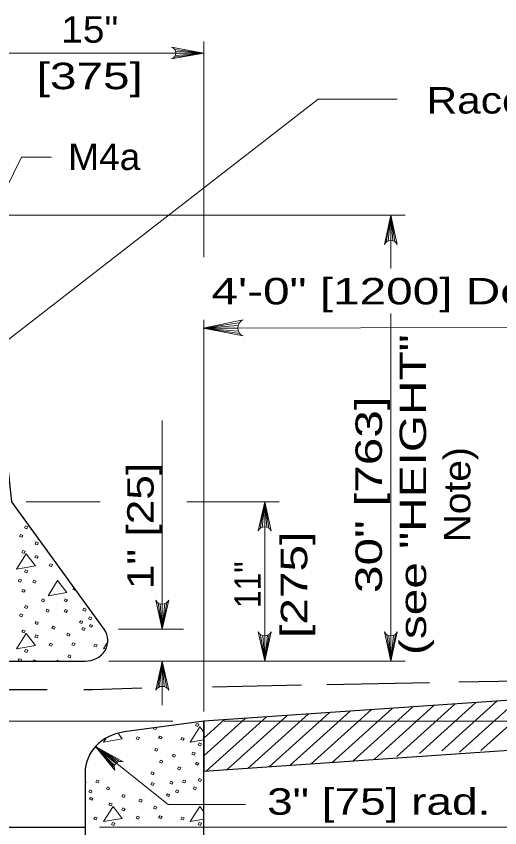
# Model space of a CAD drawing. Extents: x 1083.1 to 1123, y 697.4 to 741.4.
# Drawn here: x 1094.054 to 1096.906, y 703.761 to 708.543 of the extents above; entities that cross this region are included whole.
import ezdxf
from ezdxf.enums import TextEntityAlignment as Align

# ---------------------------------------------------------------- set-up
doc = ezdxf.new("R2010")
doc.units = 0
doc.header["$LTSCALE"] = 0.062
doc.layers.add('1', color=7, linetype='Continuous', lineweight=13)

msp = doc.modelspace()

# ---------------------------------------------------------------- linework, layer by layer
at = {"layer": '1'}
for p, q in [((1095.16083, 707.12275), (1095.16083, 708.39542)), ((1094.986, 708.30242), (1095.16083, 708.32642)), ((1094.98808, 708.34817), (1095.16083, 708.32642)), ((1094.99267, 708.3125), (1095.16083, 708.32642)), ((1094.99392, 708.33742), (1095.16083, 708.32642)), ((1094.99567, 708.32642), (1095.16083, 708.32642)), ((1093.45608, 706.21192), (1095.83508, 708.05542)), ((1095.83508, 708.05542), (1096.3005, 708.05542)), ((1093.92825, 707.3705), (1096.348, 707.3705)), ((1096.237, 707.21317), (1096.26375, 707.3705)), ((1096.24825, 707.21917), (1096.26375, 707.3705)), ((1096.26375, 707.22192), (1096.26375, 707.3705)), ((1096.27592, 707.22033), (1096.26375, 707.3705)), ((1096.28792, 707.215), (1096.26375, 707.3705)), ((1096.26375, 707.3705), (1096.26375, 707.05658)), ((1096.26375, 706.79183), (1096.26375, 704.74317)), ((1095.36967, 706.73608), (1095.15642, 706.70625)), ((1095.16083, 704.44592), (1095.16083, 706.75408)), ((1095.3625, 706.72133), (1095.15642, 706.70625)), ((1099.309, 706.71308), (1095.15642, 706.70625)), ((1095.36025, 706.70625), (1095.15642, 706.70625)), ((1095.364, 706.68708), (1095.15642, 706.70625)), ((1095.37217, 706.67333), (1095.15642, 706.70625)), ((1094.91525, 706.16133), (1094.91525, 704.93058)), ((1094.11258, 705.68267), (1094.54875, 705.68267)), ((1095.05925, 705.68267), (1095.604, 705.68267)), ((1095.493, 705.52533), (1095.51975, 705.68267)), ((1095.50425, 705.53133), (1095.51975, 705.68267)), ((1095.51975, 705.68267), (1095.51975, 704.74317)), ((1095.51975, 705.53408), (1095.51975, 705.68267)), ((1095.532, 705.5325), (1095.51975, 705.68267)), ((1095.54392, 705.52717), (1095.51975, 705.68267)), ((1094.89108, 705.08608), (1094.91525, 704.93058)), ((1094.903, 705.08075), (1094.91525, 704.93058)), ((1094.94192, 705.08792), (1094.91525, 704.93058)), ((1094.93075, 705.08192), (1094.91525, 704.93058)), ((1094.91525, 705.07917), (1094.91525, 704.93058)), ((1094.65667, 704.93058), (1095.03958, 704.93058)), ((1095.49558, 704.89867), (1095.51975, 704.74317)), ((1095.50758, 704.89342), (1095.51975, 704.74317)), ((1095.5465, 704.9005), (1095.51975, 704.74317)), ((1095.53525, 704.8945), (1095.51975, 704.74317)), ((1095.51975, 704.89175), (1095.51975, 704.74317)), ((1096.23958, 704.89867), (1096.26375, 704.74317)), ((1096.2515, 704.89342), (1096.26375, 704.74317)), ((1096.29042, 704.9005), (1096.26375, 704.74317)), ((1096.27925, 704.8945), (1096.26375, 704.74317)), ((1096.26375, 704.89175), (1096.26375, 704.74317)), ((1094.15425, 704.74317), (1094.15775, 704.75108)), ((1094.29692, 704.7495), (1094.293, 704.74317)), ((1094.30192, 704.74317), (1094.29692, 704.7495)), ((1094.4675, 704.74517), (1094.46758, 704.74542)), ((1094.46758, 704.74542), (1094.46792, 704.74525)), ((1094.59983, 704.74317), (1096.348, 704.74317)), ((1094.8885, 704.58583), (1094.91525, 704.74317)), ((1094.89967, 704.59183), (1094.91525, 704.74317)), ((1094.91525, 704.59458), (1094.91525, 704.74317)), ((1094.92742, 704.59292), (1094.91525, 704.74317)), ((1094.93942, 704.58767), (1094.91525, 704.74317)), ((1094.91525, 704.48392), (1094.91525, 704.74317)), ((1096.29883, 704.18142), (1096.64175, 704.49)), ((1096.43342, 704.19975), (1096.7655, 704.4985)), ((1096.56525, 704.2155), (1096.88925, 704.50692)), ((1096.66892, 704.20575), (1097.01292, 704.51542)), ((1096.79442, 704.21592), (1097.13667, 704.52392)), ((1095.54592, 704.121), (1095.89942, 704.43917)), ((1095.66967, 704.1295), (1096.02317, 704.44767)), ((1095.79333, 704.138), (1096.14683, 704.45608)), ((1095.917, 704.14642), (1096.27058, 704.46458)), ((1096.04075, 704.15492), (1096.39433, 704.47308)), ((1096.23058, 704.22283), (1096.51808, 704.4815)), ((1095.16083, 704.18592), (1095.40458, 704.40517)), ((1095.16083, 704.28875), (1095.28083, 704.39675)), ((1095.17475, 704.0955), (1095.52825, 704.41367)), ((1095.29842, 704.104), (1095.65192, 704.42217)), ((1095.42217, 704.1125), (1095.77567, 704.43067)), ((1092.79442, 704.3885), (1094.97683, 704.3885)), ((1095.16083, 704.32433), (1095.1365, 704.35558)), ((1095.28075, 704.3885), (1100.93725, 704.3885)), ((1100.14858, 704.3885), (1096.461, 704.3885)), ((1096.1645, 704.16342), (1096.27725, 704.26483)), ((1094.64208, 704.14075), (1094.52225, 704.241)), ((1094.63433, 704.129), (1094.52225, 704.241)), ((1094.632, 704.11792), (1094.52225, 704.241)), ((1094.65117, 704.14733), (1094.52225, 704.241)), ((1094.66308, 704.15133), (1094.52225, 704.241)), ((1095.16083, 703.85558), (1095.1365, 703.88692)), ((1094.54408, 703.76442), (1100.20558, 703.76442))]:
    msp.add_line(p, q, dxfattribs=at)
at = {"layer": '1', "lineweight": 25}
for p, q in [((1092.1595, 704.74317), (1094.45958, 704.74317)), ((1096.66467, 704.62075), (1097.23042, 704.63183)), ((1094.795, 704.5835), (1094.50333, 704.57417)), ((1095.21092, 704.59225), (1095.73708, 704.60258)), ((1095.88567, 704.6055), (1096.49117, 704.61733)), ((1094.23692, 704.57392), (1093.65075, 704.57333)), ((1094.50333, 704.57417), (1094.45267, 704.57408)), ((1095.16083, 704.3885), (1094.68975, 704.32567)), ((1095.16083, 699.49442), (1095.16083, 704.3885)), ((1096.78842, 704.20617), (1099.30092, 704.37842)), ((1095.16083, 704.09458), (1096.78842, 704.20617)), ((1094.45983, 704.08583), (1094.45983, 702.96883)), ((1093.78567, 703.76442), (1094.45983, 703.76442))]:
    msp.add_line(p, q, dxfattribs=at)
at = {"layer": '1'}
for points in [[(1094.97, 708.29208), (1095.16083, 708.32642), (1094.97, 708.36083)], [(1095.16083, 708.32642), (1093.50392, 708.32642), (1092.759, 708.32642)], [(1093.70142, 706.93558), (1094.084, 707.71383), (1094.26242, 707.71383)], [(1096.22558, 707.19875), (1096.26375, 707.3705), (1096.30192, 707.19875)], [(1095.392, 706.65917), (1095.15642, 706.70625), (1095.392, 706.75342)], [(1095.48158, 705.51092), (1095.51975, 705.68267), (1095.55792, 705.51092)], [(1094.4025, 705.16558), (1094.40025, 705.16158), (1094.38675, 705.16642), (1094.393, 705.17858)], [(1094.95342, 705.10233), (1094.91525, 704.93058), (1094.87708, 705.10233)], [(1095.55792, 704.91492), (1095.51975, 704.74317), (1095.48158, 704.91492)], [(1096.30192, 704.91492), (1096.26375, 704.74317), (1096.22558, 704.91492)], [(1094.58817, 704.84883), (1094.56817, 704.8165), (1094.58192, 704.819)], [(1094.07342, 704.74317), (1094.06617, 704.74625), (1094.0715, 704.75758)], [(1094.0715, 704.75758), (1094.085, 704.75267), (1094.08083, 704.74317)], [(1094.15775, 704.75108), (1094.17125, 704.74542), (1094.17017, 704.74317)], [(1094.87708, 704.57142), (1094.91525, 704.74317), (1094.95342, 704.57142)], [(1094.88325, 704.3515), (1094.87783, 704.34025), (1094.86442, 704.34508), (1094.86633, 704.34925)], [(1095.1365, 704.35558), (1095.08083, 704.26592), (1095.16083, 704.27992)], [(1094.5815, 704.28617), (1094.56892, 704.26592), (1094.67942, 704.28525), (1094.65633, 704.31492)], [(1094.63633, 704.10092), (1094.52225, 704.241), (1094.68508, 704.14925)], [(1094.52225, 704.241), (1094.95042, 703.89883), (1095.40592, 703.89883)], [(1094.45983, 704.03275), (1094.46658, 704.02992), (1094.46117, 704.01858), (1094.45983, 704.01908)], [(1094.45983, 703.9165), (1094.46117, 703.916), (1094.45983, 703.91317)], [(1095.1365, 703.88692), (1095.08083, 703.79717), (1095.16083, 703.81125)]]:
    msp.add_lwpolyline(points, dxfattribs=at)
at = {"layer": '1', "lineweight": 25}
for points in [[(1094.57242, 704.93058), (1094.02833, 705.68267), (1093.86025, 707.22475)], [(1099.30092, 704.67233), (1095.16083, 704.3885), (1095.16083, 704.09458)]]:
    msp.add_lwpolyline(points, dxfattribs=at)
at = {"layer": '1'}
for points in [[(1094.10833, 705.53983), (1094.12183, 705.53417), (1094.11558, 705.52283), (1094.10208, 705.5285)], [(1094.07875, 705.48967), (1094.09217, 705.48408), (1094.08683, 705.47275), (1094.07333, 705.47842)], [(1094.17033, 705.44525), (1094.18375, 705.43958), (1094.17842, 705.42833), (1094.16492, 705.43317)], [(1094.09308, 705.39517), (1094.10658, 705.39033), (1094.10117, 705.37817), (1094.08767, 705.38383)], [(1094.11192, 705.37492), (1094.05625, 705.28525), (1094.16675, 705.30467)], [(1094.16942, 705.36608), (1094.18292, 705.36042), (1094.17658, 705.34908), (1094.16317, 705.35392)], [(1094.25383, 705.31675), (1094.26733, 705.31192), (1094.26192, 705.30058), (1094.24842, 705.30542)], [(1094.10833, 705.28042), (1094.12183, 705.27558), (1094.11642, 705.26342), (1094.103, 705.26908)], [(1094.0715, 705.22625), (1094.085, 705.22142), (1094.07958, 705.20933), (1094.06617, 705.21492)], [(1094.15775, 705.21983), (1094.17125, 705.21417), (1094.16583, 705.20283), (1094.15233, 705.20767)], [(1094.29692, 705.21817), (1094.24125, 705.1285), (1094.35175, 705.14783)], [(1094.09217, 705.16567), (1094.10567, 705.16083), (1094.09942, 705.1495), (1094.08592, 705.15433)], [(1094.20808, 705.10992), (1094.2215, 705.10425), (1094.21608, 705.09292), (1094.20267, 705.09775)], [(1094.34183, 705.10992), (1094.35533, 705.10508), (1094.349, 705.09375), (1094.33558, 705.09858)], [(1094.10833, 705.07108), (1094.12183, 705.06542), (1094.11558, 705.05417), (1094.10208, 705.05975)], [(1094.07875, 705.021), (1094.09217, 705.01533), (1094.08683, 705.004), (1094.07333, 705.00967)], [(1094.235, 705.04925), (1094.24842, 705.04367), (1094.24308, 705.03233), (1094.22958, 705.038)], [(1094.34183, 705.04683), (1094.35533, 705.042), (1094.349, 705.02992), (1094.33558, 705.0355)], [(1094.45233, 705.05492), (1094.46575, 705.04925), (1094.46042, 705.038), (1094.44692, 705.04283)], [(1094.17033, 704.97658), (1094.18375, 704.97092), (1094.17842, 704.95958), (1094.16492, 704.96442)], [(1094.43258, 704.98142), (1094.446, 704.97658), (1094.44058, 704.96525), (1094.42717, 704.97008)], [(1094.48642, 705.004), (1094.49992, 704.99833), (1094.4945, 704.98708), (1094.481, 704.99192)], [(1094.09308, 704.92642), (1094.10658, 704.92158), (1094.10117, 704.9095), (1094.08767, 704.91517)], [(1094.27092, 704.94908), (1094.28433, 704.94425), (1094.27808, 704.93208), (1094.26458, 704.93775)], [(1094.44692, 704.941), (1094.46042, 704.93533), (1094.455, 704.924), (1094.4415, 704.92967)], [(1094.49092, 704.95958), (1094.50442, 704.95392), (1094.499, 704.94258), (1094.4855, 704.94825)], [(1094.11192, 704.90625), (1094.05625, 704.8165), (1094.16675, 704.83592)], [(1094.16942, 704.89733), (1094.18292, 704.89167), (1094.17658, 704.88042), (1094.16317, 704.88525)], [(1094.35708, 704.90708), (1094.37058, 704.90217), (1094.36517, 704.89092), (1094.35175, 704.89575)], [(1094.25383, 704.84808), (1094.26733, 704.84325), (1094.26192, 704.83192), (1094.24842, 704.83675)], [(1094.38767, 704.85125), (1094.40108, 704.84642), (1094.39483, 704.83517), (1094.38133, 704.84)], [(1094.51783, 704.84325), (1094.53133, 704.83833), (1094.525, 704.82708), (1094.51158, 704.83192)], [(1094.10833, 704.81167), (1094.12183, 704.80683), (1094.11642, 704.79475), (1094.103, 704.80042)], [(1094.36342, 704.77933), (1094.37683, 704.7745), (1094.3715, 704.76325), (1094.358, 704.76808)], [(1095.11767, 704.37575), (1095.13108, 704.37092), (1095.12575, 704.35883), (1095.11225, 704.3645)], [(1094.7665, 704.29742), (1094.78, 704.29258), (1094.77458, 704.28125), (1094.76108, 704.28608)], [(1094.90033, 704.30067), (1094.91375, 704.29575), (1094.9075, 704.2845), (1094.894, 704.28933)], [(1095.0305, 704.29258), (1095.044, 704.28775), (1095.03767, 704.27642), (1095.02425, 704.28125)], [(1095.13292, 704.26108), (1095.14633, 704.25617), (1095.141, 704.24408), (1095.1275, 704.24975)], [(1094.87608, 704.22875), (1094.8895, 704.22383), (1094.88417, 704.21258), (1094.87067, 704.21742)], [(1095.09608, 704.20692), (1095.10958, 704.20208), (1095.10417, 704.18992), (1095.09067, 704.19558)], [(1094.90567, 704.15925), (1094.91917, 704.15358), (1094.91292, 704.14225), (1094.89942, 704.14708)], [(1094.98025, 704.19475), (1094.99367, 704.18908), (1094.98833, 704.17783), (1094.97483, 704.1835)], [(1095.01075, 704.11958), (1095.02425, 704.11475), (1095.01883, 704.10267), (1095.00542, 704.10833)], [(1095.11675, 704.14625), (1095.13017, 704.14142), (1095.12392, 704.13017), (1095.11042, 704.135)], [(1094.8545, 704.0905), (1094.868, 704.08567), (1094.86167, 704.07433), (1094.84825, 704.07925)], [(1094.52942, 704.04208), (1094.54292, 704.03717), (1094.53658, 704.02508), (1094.52317, 704.03075)], [(1094.8545, 704.0275), (1094.868, 704.02267), (1094.86167, 704.0105), (1094.84825, 704.01617)], [(1094.965, 704.03558), (1094.97842, 704.02992), (1094.97308, 704.01858), (1094.95958, 704.02342)], [(1095.04133, 704.04208), (1095.05475, 704.03717), (1095.0485, 704.02508), (1095.035, 704.03075)], [(1095.13292, 704.05175), (1095.14633, 704.04608), (1095.14008, 704.03475), (1095.12658, 704.04042)], [(1094.48725, 703.98467), (1094.50067, 703.979), (1094.49533, 703.96767), (1094.48183, 703.9725)], [(1094.59142, 704.00167), (1094.60492, 703.996), (1094.5995, 703.98467), (1094.586, 703.99033)], [(1094.94517, 703.962), (1094.95867, 703.95717), (1094.95333, 703.94592), (1094.93983, 703.95075)], [(1094.99908, 703.98467), (1095.01258, 703.979), (1095.00717, 703.96767), (1094.99367, 703.9725)], [(1095.10325, 704.00167), (1095.11675, 703.996), (1095.11133, 703.98467), (1095.09783, 703.99033)], [(1094.49175, 703.94025), (1094.50517, 703.93458), (1094.49983, 703.92325), (1094.48633, 703.92892)], [(1094.683, 703.95717), (1094.6965, 703.9515), (1094.69108, 703.94025), (1094.67758, 703.94508)], [(1094.78358, 703.92975), (1094.797, 703.92483), (1094.79075, 703.91275), (1094.77725, 703.91842)], [(1094.62467, 703.88692), (1094.56892, 703.79717), (1094.67942, 703.81658)], [(1094.60575, 703.90708), (1094.61925, 703.90225), (1094.61383, 703.89008), (1094.60042, 703.89575)], [(1094.68208, 703.878), (1094.69558, 703.87233), (1094.68925, 703.861), (1094.67583, 703.86592)], [(1094.86975, 703.88767), (1094.88325, 703.88283), (1094.87783, 703.8715), (1094.86442, 703.87642)], [(1094.51867, 703.82383), (1094.53217, 703.819), (1094.52583, 703.80767), (1094.51242, 703.8125)], [(1094.7665, 703.82867), (1094.78, 703.82383), (1094.77458, 703.8125), (1094.76108, 703.81742)], [(1094.90033, 703.83192), (1094.91375, 703.82708), (1094.9075, 703.81575), (1094.894, 703.82058)], [(1095.0305, 703.82383), (1095.044, 703.819), (1095.03767, 703.80767), (1095.02425, 703.8125)], [(1094.621, 703.79233), (1094.6345, 703.7875), (1094.62908, 703.77533), (1094.61567, 703.781)], [(1095.13292, 703.79233), (1095.14633, 703.7875), (1095.141, 703.77533), (1095.1275, 703.781)]]:
    msp.add_lwpolyline(points, close=True, dxfattribs=at)
msp.add_arc((1095.41103, 706.70634), 0.05085, 112.08782, 247.91395, dxfattribs=at)
for centre, major_axis, ratio, start_param, end_param in [((1094.95458, 708.32649), (0.04119, 0), 0.9, 5.0978633, 7.4684764), ((1096.26379, 707.1849), (0.04119, 0), 0.9, 0.3855052, 2.7561184), ((1095.51979, 705.49707), (0.04119, 0), 0.9, 0.3855052, 2.7561184), ((1094.91517, 705.11618), (-0.04119, 0), 0.9, 0.3855052, 2.7561184), ((1095.51971, 704.92878), (-0.04119, 0), 0.9, 0.3855052, 2.7561184), ((1096.2637, 704.92878), (-0.04119, 0), 0.9, 0.3855052, 2.7561184), ((1094.91526, 704.55755), (0.04119, 0), 0.9, 0.3855052, 2.7561184), ((1094.67197, 704.11567), (0.03911, -0.00825), 0.899905, 1.4222416, 3.7928547)]:
    msp.add_ellipse(centre, major_axis=major_axis, ratio=ratio, start_param=start_param, end_param=end_param, dxfattribs=at)
at = {"layer": '1', "lineweight": 25}
for centre, major_axis, start_param, end_param in [((1094.45957, 704.86438), (0.1347, 0), 4.712389, 6.860469), ((1094.72924, 704.08585), (-0.2694, 0), 4.859526, 6.2831853)]:
    msp.add_ellipse(centre, major_axis=major_axis, ratio=0.899905, start_param=start_param, end_param=end_param, dxfattribs=at)

# ---------------------------------------------------------------- texts
at = {"layer": '1'}
for s, width, p in [('15"', 1.1, (1094.48737, 708.3875)), ('[375]', 1.35, (1094.48733, 708.1135))]:
    msp.add_text(s, height=0.156, dxfattribs=dict(at, width=width)).set_placement(p, align=Align.CENTER)
for s, width, p in [('Raceway', 1.2, (1096.47417, 707.97017)), ('M4a', 1.05, (1094.35975, 707.63742)), ('4\'-0" [1200] Depressed Apron', 1.35, (1095.2055, 706.84533)), ('3" [75] rad.', 1.3, (1095.53358, 703.83792))]:
    msp.add_text(s, height=0.156, dxfattribs=dict(at, width=width)).set_placement(p)
for s, width, p in [('(see "HEIGHT"', 1.35, (1096.47183, 705.72392)), ('30" [763]', 1.4, (1096.21117, 705.72396)), ('Note)', 1.1, (1096.7325, 705.72392)), ('[275]', 1.35, (1095.77067, 705.19292)), ('11"', 0.9, (1095.49667, 705.19287))]:
    msp.add_text(s, height=0.156, rotation=90, dxfattribs=dict(at, width=width)).set_placement(p, align=Align.CENTER)
at = {"layer": '1', "width": 1.25}
msp.add_text('1" [25]', height=0.156, rotation=90, dxfattribs=at).set_placement((1094.86425, 705.16675))

doc.saveas('drawing.dxf')
